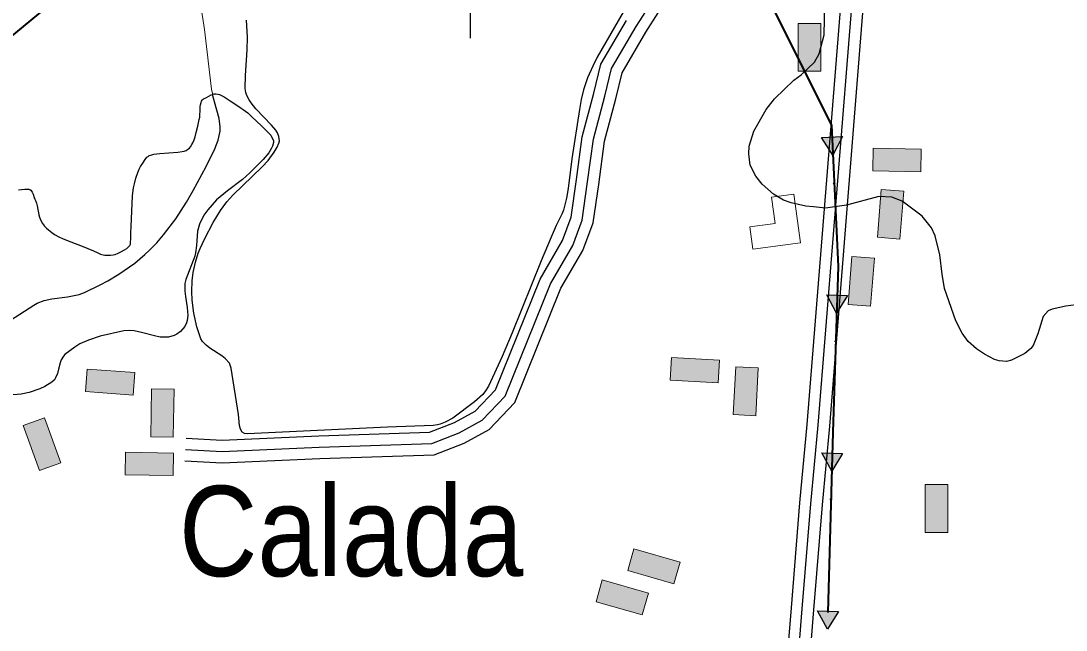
# Model space of a CAD drawing. Extents: x -64005 to -55000, y -89025 to -80000.
# Drawn here: x -59043 to -58117, y -81099 to -80559 of the extents above; entities that cross this region are included whole.
import ezdxf
from ezdxf.enums import TextEntityAlignment as Align

# ---------------------------------------------------------------- set-up
doc = ezdxf.new("R2010")
doc.units = 0
doc.header["$LTSCALE"] = 32
doc.linetypes.add('DOT_DASHED', pattern=[7.7, 5, -1.2, 0.3, -1.2])
doc.linetypes.add('LONG_DASHED', pattern=[7.5, 6, -1.5])
for name, color, linetype, lineweight in [('1', 7, 'Continuous', 25), ('18', 7, 'Continuous', 25), ('2', 7, 'Continuous', 25), ('24', 7, 'Continuous', 25), ('32', 7, 'Continuous', 25), ('39', 7, 'LONG_DASHED', 25), ('6', 7, 'Continuous', 25), ('7', 7, 'Continuous', 13), ('8', 7, 'Continuous', 25)]:
    doc.layers.add(name, color=color, linetype=linetype, lineweight=lineweight)
doc.layers.add('45', color=7, linetype='Continuous')

msp = doc.modelspace()

# ---------------------------------------------------------------- hatches: boundary and pattern name
at = {"layer": '18'}
for points in [[(-58314.89, -80661.74), (-58323.39, -80678.17), (-58333.37, -80662.59)], [(-58310.39, -80802.32), (-58320.15, -80818.04), (-58328.88, -80801.73)], [(-58314.74, -80942.21), (-58324.42, -80957.97), (-58333.23, -80941.71)], [(-58318.48, -81082.16), (-58328.16, -81097.92), (-58336.98, -81081.66)]]:
    msp.add_hatch(color=256, dxfattribs=at).paths.add_polyline_path(points)
at = {"layer": '7'}
for points in [[(-58334.02, -80603.9), (-58334.02, -80561.4), (-58354.02, -80561.4), (-58354.02, -80603.9)], [(-58287.98, -80692.01), (-58245.49, -80692.89), (-58245.08, -80672.89), (-58287.57, -80672.01)], [(-58280.46, -80708.48), (-58283.85, -80750.84), (-58263.92, -80752.44), (-58260.53, -80710.08)], [(-58306.52, -80767.89), (-58309.92, -80810.25), (-58289.98, -80811.85), (-58286.58, -80769.49)], [(-58467.43, -80877.39), (-58424.98, -80879.62), (-58423.93, -80859.65), (-58466.38, -80857.42)], [(-58941.9, -80870.68), (-58984.28, -80867.54), (-58985.76, -80887.48), (-58943.38, -80890.62)], [(-58409.45, -80865.47), (-58411.68, -80907.92), (-58391.71, -80908.97), (-58389.48, -80866.52)], [(-58927.22, -80884.95), (-58927.88, -80927.44), (-58907.88, -80927.75), (-58907.22, -80885.26)], [(-59040.8, -80917.48), (-59026.42, -80957.48), (-59007.6, -80950.72), (-59021.98, -80910.72)], [(-58950.57, -80961.23), (-58908.07, -80961.91), (-58907.75, -80941.91), (-58950.25, -80941.23)], [(-58241.51, -80969.68), (-58241.51, -81012.18), (-58221.51, -81012.18), (-58221.51, -80969.68)], [(-58505.14, -81046.1), (-58464.27, -81057.77), (-58458.78, -81038.54), (-58499.65, -81026.87)], [(-58533.18, -81073.6), (-58492.31, -81085.27), (-58486.82, -81066.04), (-58527.69, -81054.37)]]:
    msp.add_hatch(color=256, dxfattribs=at).paths.add_polyline_path(points)

# ---------------------------------------------------------------- linework, layer by layer
at = {"layer": '1'}
for points in [[(-58271.08, -80715.3), (-58282.55, -80714.63), (-58311.42, -80722.34), (-58329.92, -80725.12), (-58340.7, -80723.79), (-58347.22, -80723.39), (-58360.25, -80720.4), (-58367.12, -80717.88), (-58375.99, -80712.67), (-58385.93, -80703.84), (-58391.8, -80696.82), (-58396.62, -80687.03), (-58397.99, -80677.02), (-58397.44, -80670.1), (-58393.36, -80656.92), (-58382.41, -80637.63), (-58374.97, -80628.38), (-58358.03, -80611.81), (-58351.51, -80606.99), (-58339.53, -80595.66), (-58335.47, -80588.48), (-58331.14, -80571.64), (-58330.48, -80543.57)], [(-58099.27, -80809.53), (-58117.06, -80811.73), (-58129.2, -80814.38), (-58132.66, -80815.92), (-58137.08, -80821), (-58141.71, -80836.37), (-58145.91, -80846.6), (-58147.91, -80849.29), (-58153.16, -80853.65), (-58165.24, -80859.6), (-58169.41, -80860.9), (-58175.94, -80860.36), (-58180.29, -80858.98), (-58188.97, -80854.51), (-58196.08, -80849.73), (-58203.48, -80843.06), (-58208.91, -80835.75), (-58214.54, -80824.91), (-58224.42, -80796.29), (-58226.57, -80783.54), (-58228.69, -80766.34), (-58232.77, -80749.49), (-58236.01, -80742.39), (-58244.36, -80732.16), (-58261.88, -80718.87), (-58271.08, -80715.3)]]:
    msp.add_lwpolyline(points, dxfattribs=at)
at = {"layer": '18'}
msp.add_line((-58325.75, -81007.96), (-58327.73, -81081.91), dxfattribs=at)
at = {"layer": '18', "linetype": 'DOT_DASHED', "lineweight": 40}
for points in [[(-62477.87, -83403.87), (-62367.98, -83378.64), (-62216.73, -83247.74), (-62089.34, -83137.49), (-61996.3, -83056.97), (-61098.84, -82280.26), (-60868.7, -82080.1), (-60312.19, -81596.09), (-60219.71, -81521.05), (-59047.52, -80569.92), (-58561.43, -80162.65), (-58367.89, -80000.48)], [(-58533.19, -80215.56), (-58484.36, -80323.89), (-58375.02, -80550.79), (-58324.62, -80651.59), (-58318.83, -80776.6), (-58323.49, -80923.33), (-58331.23, -81212.92), (-58335.52, -81363.6), (-58303.61, -81482.29), (-58273.33, -81806.29), (-58260.06, -81954.23), (-58246.44, -82095.74), (-58226.31, -82245.99)]]:
    msp.add_lwpolyline(points, dxfattribs=at)
at = {"layer": '18'}
for points in [[(-58352.97, -80594.89), (-58324.62, -80651.59), (-58324.13, -80662.16)], [(-58321.08, -80728.11), (-58318.83, -80776.6), (-58319.64, -80802.03)], [(-58321.73, -80868.01), (-58323.49, -80923.33), (-58323.99, -80941.96)]]:
    msp.add_lwpolyline(points, dxfattribs=at)
for points in [[(-58314.89, -80661.74), (-58323.39, -80678.17), (-58333.37, -80662.59)], [(-58310.39, -80802.32), (-58320.15, -80818.04), (-58328.88, -80801.73)], [(-58314.74, -80942.21), (-58324.42, -80957.97), (-58333.23, -80941.71)], [(-58318.48, -81082.16), (-58328.16, -81097.92), (-58336.98, -81081.66)]]:
    msp.add_lwpolyline(points, close=True, dxfattribs=at)
for centre in [(-58364.15, -80572.53), (-58322.23, -80703.14), (-58320.94, -80843.03), (-58325.08, -80982.96)]:
    msp.add_circle(centre, 0.5, dxfattribs=at)
at = {"layer": '2', "lineweight": 13}
msp.add_lwpolyline([(-58872.98, -80624.35), (-58873.24, -80623.32), (-58873.42, -80622.24), (-58873.87, -80619.56), (-58880.13, -80566.9), (-58883.54, -80545.94), (-58891.39, -80504.22), (-58894.47, -80491.55), (-58902.39, -80466.59), (-58906.1, -80454.1), (-58907.65, -80447.81), (-58909.48, -80437.33), (-58909.91, -80431.94), (-58909.64, -80423.92), (-58907.92, -80416.27), (-58906.4, -80412.69), (-58901.1, -80402.23), (-58889.84, -80385.23), (-58887.15, -80379.37), (-58886.37, -80376.34), (-58886.14, -80370.84), (-58886.65, -80367.06), (-58888.48, -80359.34), (-58890.48, -80350.67)], dxfattribs=at)
at = {"layer": '2'}
msp.add_lwpolyline([(-59117.8, -80866.16), (-59031.46, -80810.98), (-59028.48, -80809.33), (-59022.15, -80806.96), (-59015.44, -80805.49), (-59001.54, -80803.62), (-58991.29, -80801.49), (-58986.41, -80799.7), (-58972.53, -80793.06), (-58965.8, -80789.45), (-58955.99, -80783.61), (-58941.96, -80773.71), (-58933.09, -80766.25), (-58928.81, -80762.23), (-58922.59, -80755.81), (-58916.49, -80748.83), (-58905.6, -80734.57), (-58896.03, -80719.78), (-58890.12, -80709.57), (-58878.79, -80688.1), (-58871.01, -80672.67), (-58868.02, -80664.88), (-58866.41, -80656.99), (-58866.29, -80652.99), (-58867.25, -80645.6), (-58871.35, -80630.79), (-58872.98, -80624.35)], dxfattribs=at)
at = {"layer": '24'}
for points in [[(-58489.41, -80516.86), (-58532.19, -80591.5), (-58536.23, -80599.46), (-58540.76, -80609.75), (-58544.29, -80620.31), (-58546.37, -80628.92), (-58547.98, -80637.62), (-58554.57, -80681.34), (-58557.84, -80707.53), (-58559.4, -80716.17), (-58562.11, -80726.84), (-58563.27, -80729.94), (-58568.44, -80740.29), (-58573.05, -80750.73), (-58581.89, -80771.77), (-58607.48, -80835.41), (-58616.45, -80856.55), (-58628.54, -80882.71), (-58631.09, -80886.95), (-58633.56, -80889.99), (-58640.95, -80896.72), (-58660.23, -80911.02), (-58666.87, -80914.74), (-58671.49, -80916.48), (-58673.88, -80917.06), (-58677.58, -80917.53), (-58717.91, -80919.11), (-58842.15, -80924.96), (-58844.82, -80924.59), (-58846.91, -80923.35), (-58848.29, -80920.68), (-58849.11, -80917.45), (-58850.11, -80907.74), (-58856.58, -80866.75), (-58857.35, -80864.08), (-58858.17, -80862.45), (-58861.78, -80858.2), (-58864.9, -80855.74), (-58875.47, -80848.94), (-58878.71, -80846.5), (-58882.06, -80843.06)], [(-58882.06, -80843.06), (-58883.54, -80840.71), (-58887.1, -80830.17), (-58889.8, -80817.95), (-58891.15, -80806.6), (-58891.44, -80798.96), (-58891.07, -80789.45), (-58890.17, -80781.96), (-58888.24, -80772.87), (-58885.71, -80765.04), (-58883.95, -80760.67), (-58880.01, -80751.97), (-58872.5, -80737.87), (-58866.01, -80727.17), (-58860.38, -80719.52), (-58855.14, -80713.65), (-58828.98, -80688.47), (-58823.82, -80682.82), (-58818.35, -80675.56), (-58815.74, -80671.06), (-58814.24, -80667.61), (-58813.84, -80665.32), (-58814.33, -80661.5), (-58815.62, -80658.44), (-58817.02, -80656.13), (-58820.71, -80651.48), (-58834.75, -80636.99), (-58838.94, -80631.9), (-58840.68, -80629.29), (-58842.71, -80625.28), (-58843.59, -80622.55), (-58844.06, -80619.05), (-58843.88, -80607.7), (-58842.38, -80584.91), (-58842.07, -80573.52), (-58842.86, -80558.45)]]:
    msp.add_lwpolyline(points, dxfattribs=at)
at = {"layer": '32'}
msp.add_line((-58644.75, -80534.63), (-58644.75, -80574.63), dxfattribs=at)
at = {"layer": '39', "linetype": 'Continuous'}
for points in [[(-58336.37, -80917.36), (-58295.8, -80410.35), (-58282.46, -80253.82)], [(-58376.92, -81439.44), (-58373.5, -81393.1), (-58367.66, -81313.45), (-58363.2, -81255.07), (-58358.03, -81172.66), (-58350.48, -81079.95), (-58342.93, -80986.9), (-58336.37, -80917.36)]]:
    msp.add_lwpolyline(points, dxfattribs=at)
at = {"layer": '39'}
msp.add_lwpolyline([(-58897.15, -80938.78), (-58864.56, -80940.68), (-58778.47, -80936.72), (-58678.87, -80933.54), (-58654.4, -80924.04), (-58634.14, -80912.95), (-58613.88, -80891.59), (-58573.61, -80792.05), (-58553.96, -80758.13), (-58545.42, -80735.64), (-58540.69, -80701.82), (-58535.63, -80663.83), (-58525.5, -80625.83), (-58519.59, -80601.3), (-58497.64, -80564.1), (-58465.59, -80513.64)], dxfattribs=at)
at = {"layer": '6'}
for points in [[(-58292.98, -80259.58), (-58305.76, -80409.52), (-58346.34, -80916.54), (-58352.89, -80986.02), (-58360.45, -81079.14), (-58368, -81171.94), (-58373.17, -81254.38), (-58377.63, -81312.7), (-58383.47, -81392.37), (-58386, -81426.68)], [(-58273.78, -80269.68), (-58285.84, -80411.18), (-58326.4, -80918.18), (-58332.97, -80987.78), (-58340.51, -81080.76), (-58348.06, -81173.38), (-58353.23, -81255.76), (-58357.69, -81314.2), (-58363.53, -81393.83), (-58366.39, -81432.64)]]:
    msp.add_lwpolyline(points, dxfattribs=at)
at = {"layer": '7'}
for points in [[(-58334.02, -80603.9), (-58334.02, -80561.4), (-58354.02, -80561.4), (-58354.02, -80603.9)], [(-58287.98, -80692.01), (-58245.49, -80692.89), (-58245.08, -80672.89), (-58287.57, -80672.01)], [(-58394.22, -80761.52), (-58352.1, -80755.88), (-58357.87, -80712.71), (-58377.72, -80715.37), (-58374.6, -80738.71), (-58396.87, -80741.7)], [(-58280.46, -80708.48), (-58283.85, -80750.84), (-58263.92, -80752.44), (-58260.53, -80710.08)], [(-58306.52, -80767.89), (-58309.92, -80810.25), (-58289.98, -80811.85), (-58286.58, -80769.49)], [(-58467.43, -80877.39), (-58424.98, -80879.62), (-58423.93, -80859.65), (-58466.38, -80857.42)], [(-58941.9, -80870.68), (-58984.28, -80867.54), (-58985.76, -80887.48), (-58943.38, -80890.62)], [(-58409.45, -80865.47), (-58411.68, -80907.92), (-58391.71, -80908.97), (-58389.48, -80866.52)], [(-58927.22, -80884.95), (-58927.88, -80927.44), (-58907.88, -80927.75), (-58907.22, -80885.26)], [(-59040.8, -80917.48), (-59026.42, -80957.48), (-59007.6, -80950.72), (-59021.98, -80910.72)], [(-58950.57, -80961.23), (-58908.07, -80961.91), (-58907.75, -80941.91), (-58950.25, -80941.23)], [(-58241.51, -80969.68), (-58241.51, -81012.18), (-58221.51, -81012.18), (-58221.51, -80969.68)], [(-58505.14, -81046.1), (-58464.27, -81057.77), (-58458.78, -81038.54), (-58499.65, -81026.87)], [(-58533.18, -81073.6), (-58492.31, -81085.27), (-58486.82, -81066.04), (-58527.69, -81054.37)]]:
    msp.add_lwpolyline(points, close=True, dxfattribs=at)
at = {"layer": '7', "lineweight": 25}
for points in [[(-58968.51, -80766.67), (-58966.03, -80766.84), (-58963.58, -80766.77), (-58961.11, -80766.45), (-58959.28, -80765.99), (-58956.57, -80764.98), (-58953.87, -80763.6), (-58951.11, -80762.02), (-58949.12, -80760.72), (-58947.81, -80759.64), (-58946.98, -80758.75), (-58946.47, -80758.04), (-58945.9, -80756.87), (-58945.64, -80755.58), (-58945.44, -80751.99), (-58945.34, -80746.6), (-58945.21, -80741.21), (-58944.63, -80727.69), (-58943.95, -80714.17), (-58943.73, -80711.55), (-58943.04, -80707), (-58942.31, -80703.62), (-58940.93, -80698.59), (-58939.29, -80693.57), (-58938.03, -80690.47), (-58936.89, -80688.27), (-58934.94, -80685.09), (-58932.75, -80681.95), (-58931.17, -80679.98), (-58930.25, -80679.18), (-58929.16, -80678.57), (-58926.81, -80677.8), (-58925.04, -80677.39), (-58922.36, -80676.97), (-58919.66, -80676.67), (-58911.74, -80676.03), (-58903.82, -80675.41), (-58900.09, -80675.04), (-58898.25, -80674.65), (-58897.33, -80674.34), (-58896.43, -80673.93), (-58894.83, -80672.91), (-58893.63, -80671.85), (-58892.71, -80670.81), (-58891.35, -80668.78), (-58890.51, -80667.12), (-58889.48, -80664.52), (-58888.61, -80661.89), (-58887.52, -80658.09), (-58886.1, -80652.39), (-58884.81, -80646.68), (-58884.47, -80644.52), (-58884.19, -80636.84), (-58884.02, -80634.93), (-58883.79, -80633.51), (-58883.21, -80631.41), (-58882.79, -80630.37), (-58882.28, -80629.35), (-58881.95, -80628.88), (-58881.22, -80628.25), (-58878.48, -80627.03)], [(-58878.48, -80627.03), (-58874.24, -80624.84), (-58872.98, -80624.35)], [(-58872.98, -80624.35), (-58871.6, -80623.95), (-58870.81, -80623.85), (-58870.03, -80623.86), (-58868.44, -80624.11), (-58867.06, -80624.52), (-58864.65, -80625.56), (-58862.86, -80626.56), (-58857.57, -80629.99), (-58852.4, -80633.34), (-58848.63, -80635.84), (-58845.88, -80637.75), (-58841.9, -80640.79), (-58839.99, -80642.42), (-58838.15, -80644.14), (-58829.81, -80652.27), (-58821.47, -80660.41)], [(-58821.47, -80660.41), (-58819.21, -80665.32), (-58819.16, -80666.98), (-58819.87, -80670.04), (-58820.71, -80672.08), (-58823.12, -80676.12), (-58828.12, -80682.11), (-58839.93, -80693.76), (-58846.45, -80699.61), (-58859.83, -80709.66), (-58866.33, -80714.9), (-58869.44, -80717.81), (-58877.36, -80726.59), (-58880.74, -80731.38), (-58884.75, -80739.23), (-58886.4, -80745.41), (-58887.44, -80758.2), (-58888.19, -80764.49), (-58888.91, -80767.55), (-58896.82, -80788.39), (-58897.58, -80791.66), (-58897.7, -80798.55), (-58897.12, -80803.32), (-58895.57, -80812.96), (-58895.12, -80820.03), (-58895.66, -80824.55), (-58896.28, -80826.72), (-58897.76, -80829.86), (-58901.4, -80834.21), (-58904.82, -80836.73), (-58907.16, -80837.91), (-58911.98, -80839.24), (-58914.44, -80839.46), (-58919.45, -80839.19), (-58924.54, -80838.24), (-58934.83, -80835.45), (-58942.49, -80833.76), (-58946.26, -80833.39), (-58951.79, -80833.79), (-58972.72, -80838.52), (-58983.12, -80841.88), (-58990.57, -80845.29), (-58995.2, -80848.07), (-59003.85, -80854.63), (-59005.23, -80856.06), (-59007.23, -80859.49), (-59008.14, -80862.07), (-59009.49, -80867.56), (-59010.57, -80871.63), (-59012.12, -80875.35), (-59013.21, -80876.98), (-59015.36, -80879.05), (-59021.78, -80882.96), (-59026.26, -80885.04), (-59035.58, -80888.35), (-59042.67, -80889.73), (-59057.21, -80890.97)], [(-59044.97, -80708.7), (-59042.35, -80708.57), (-59039.39, -80708.25), (-59037.91, -80708.13), (-59036.44, -80708.15), (-59035.73, -80708.27), (-59035.13, -80708.5), (-59034.16, -80709.18), (-59033.45, -80710.02), (-59032.91, -80710.9), (-59032.11, -80712.67), (-59031.11, -80715.57), (-59030.62, -80716.99), (-59030.1, -80718.29), (-59029.16, -80720.8), (-59028.56, -80723.06), (-59026.96, -80731.1), (-59026.44, -80733.06), (-59025.95, -80734.49), (-59025.01, -80736.58), (-59023.77, -80738.57), (-59021.91, -80740.89), (-59020.15, -80742.76), (-59018.53, -80744.28), (-59015.5, -80746.69), (-59013.1, -80748.32), (-59009.33, -80750.46), (-59005.4, -80752.3), (-58998.7, -80755.02), (-58988.6, -80758.88), (-58978.58, -80762.86), (-58975.43, -80764.29), (-58972.24, -80765.72), (-58970.14, -80766.38), (-58968.51, -80766.67)]]:
    msp.add_lwpolyline(points, dxfattribs=at)
at = {"layer": '8'}
msp.add_lwpolyline([(-58897.56, -80948.77), (-58864.62, -80950.69), (-58778.08, -80946.71), (-58676.84, -80943.48), (-58650.17, -80933.13), (-58627.96, -80920.97), (-58605.31, -80897.1), (-58564.42, -80796.01), (-58544.9, -80762.44), (-58535.67, -80738.14), (-58530.89, -80703.98), (-58525.8, -80665.79), (-58515.81, -80628.29), (-58510.21, -80605.09), (-58489.11, -80569.32), (-58456.27, -80517.61)], dxfattribs=at)
at = {"layer": '8', "linetype": 'LONG_DASHED'}
msp.add_lwpolyline([(-58896.57, -80928.8), (-58864.5, -80930.67), (-58778.86, -80926.73), (-58680.9, -80923.6), (-58658.63, -80914.95), (-58640.32, -80904.93), (-58622.44, -80886.08), (-58582.8, -80788.09), (-58563.02, -80753.82), (-58555.17, -80733.14), (-58550.49, -80699.66), (-58545.46, -80661.87), (-58535.19, -80623.37), (-58528.96, -80597.51), (-58506.17, -80558.88)], dxfattribs=at)

# ---------------------------------------------------------------- texts
at = {"layer": '45', "width": 0.9}
msp.add_text('Calada', height=80, rotation=0.007, dxfattribs=at).set_placement((-58750.31, -81050.97), align=Align.CENTER)

doc.saveas('drawing.dxf')
